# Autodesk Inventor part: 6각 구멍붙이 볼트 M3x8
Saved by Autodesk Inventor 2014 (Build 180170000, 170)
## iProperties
Created: 2026-09
Part Number: 6각 구멍붙이 볼트 M3x8
Material: 일반
Document SubType Name: Modeling
Designer: dg
Density: 1 g/cm^3
Appearance: 기본값
Author: dg
Author: jhkim
Description: 6각 소켓 머리 캡 나사
Creation Date: 2026-08-27
Sending System: Autodesk Inventor 2027
Preprocessor: ST-DEVELOPER v20.1
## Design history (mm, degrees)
node "6각 구멍붙이 볼트 M3x81"
body "Solid1"
node "기준1"
